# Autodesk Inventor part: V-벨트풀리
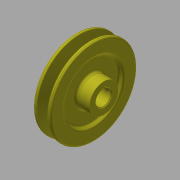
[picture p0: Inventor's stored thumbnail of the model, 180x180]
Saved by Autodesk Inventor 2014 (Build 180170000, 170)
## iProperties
Created: 2015-09
Part Number: V-벨트풀리
Material: 강철, 연강
Document SubType Name: Modeling
Designer: mduedu
Density: 7.86 g/cm^3
Mass: 779.014 g
Surface Area: 277.465 cm^2
Volume: 99.1112 cm^3
Appearance: 강철
Author: mduedu
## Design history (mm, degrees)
sketch "스케치1"
  geometry: L1 (-10, 0)-(10, 0); L2 (-10, 0)-(-10, 48); L3 (-10, 48)-(-5.976, 48); L4 (-5.976, 48)-(-2.154, 35.5); L5 (-2.154, 35.5)-(2.154, 35.5); L6 (2.154, 35.5)-(5.976, 48); L7 (5.976, 48)-(10, 48); L8 (10, 48)-(10, 0); L9 (0, 0)-(0, 35.5); L10 (-10, 43.5)-(10, 43.5); 3 further points
  constraints: 20 end point, 6 point on line, 3 perpendicular, 2 midpoint, 2 parallel, 2 symmetric about line, 1 coincident, 1 collinear, 1 equal length, 1 horizontal, 1 vertical, 1 vertical alignment
  dimensions: "d0" = 20 distance between parallel lines of L8 L2; "d2" = 96 diameter of L3 L1; "d3" = 87 diameter of L10 L1; "d4" = 4.5 distance between parallel lines of L10 L3 (derived); "d5" = 8 distance between parallel lines of L5 L10; "d6" = 9.2 distance of point (4.6, 43.5) point (-4.6, 43.5); "d7" = 34 deg angle of L6 L4
revolve "회전1" sketch "스케치1" stored, may be unused: angle "d8" = 90 deg
sketch "스케치2"
  geometry: C1 r 16 at (0, 0); 1 further point
  constraints: 1 centre point, 1 coincident
  dimensions: "d9" = 32 diameter of C1
extrude "돌출1" join sketch "스케치2" distance "d10" = 11; taper "d11" = 0 deg
fillet "모깎기1" dims "d12" = 1, "d13" = 0.5, "d14" = 2
sketch "스케치3"
  geometry: C1 r 16 at (0, 0) reference; C2 r 32 at (0, 0); 1 further point
  constraints: 1 centre point, 1 coincident
  dimensions: "d15" = 64 diameter of C2
extrude "돌출2" cut sketch "스케치3" distance "d16" = 4; taper "d17" = 0 deg
fillet "모깎기2" dims "d18" = 3
fillet "모깎기3" dims "d19" = 3
fillet "모깎기4" dims "d20" = 3
sketch "스케치4"
  geometry: C1 r 8.5 at (0, 0); 1 further point
  constraints: 1 centre point, 1 coincident
  dimensions: "d21" = 17 diameter of C1
extrude "돌출3" cut sketch "스케치4" stored distance "d22" = 4; taper "d23" = 0 deg
sketch "스케치5"
  geometry: L1 (-2.5, 8.124)-(2.5, 8.124); L2 (2.5, 8.124)-(2.5, 10.8); L3 (2.5, 10.8)-(-2.5, 10.8); L4 (-2.5, 10.8)-(-2.5, 8.124); A1 r 8.5 centre (0, 0) between (-2.5, 8.124) and (2.5, 8.124) reference; 2 further points
  constraints: 8 end point, 3 point on circle, 2 parallel, 1 horizontal, 1 perpendicular, 1 vertical alignment
  dimensions: "d24" = 5 distance of L2.end L3.end; "d26" = 19.3 distance from line of L3 point (0, -8.5)
extrude "돌출4" cut sketch "스케치5" stored distance "d27" = 4; taper "d28" = 0 deg
chamfer "모따기1" distance "d29" = 1; stored, may be unused: second distance "d30" = 2, angle "d31" = 45 deg
node "작업 평면1"
sketch "스케치6"
  geometry: L1 (-11, 16)-(-11, -16) reference; 2 further points
  constraints: 1 horizontal alignment
  dimensions: "d32" = 5 distance from line of point (-6, 0) L1
hole "구멍1" sketch "스케치6" at (-6, 0) diameter "d33" = 3.242; stored, may be unused: countersink angle "d37" = 90 deg, drill point angle "d39" = 118 deg; dims "d34" = 6, "d35" = 4, "d36" = 2, "d38" = 8
node "솔리드1"
mirror "대칭1"
